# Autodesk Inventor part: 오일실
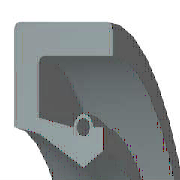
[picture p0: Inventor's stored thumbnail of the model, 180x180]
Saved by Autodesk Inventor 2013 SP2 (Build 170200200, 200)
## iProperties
IsCustomPart: 1
Created: 2015-10
Part Number: 오일실
Material: 고무
Description: 오일-실
Document SubType Name: Modeling
Standard: KS B 2804
Designer: mdu
Standards Organization: KS
Language: ko-KR
Size Designation: S - 25 38 8
Categories: <MemberInstance><Categories><Category DisplayName="샤프트 부품" InternalName="7f7aeb1f-a693-4053-b835-cee3144e0d98" Mnemonic="SHFT"><Category DisplayName="실링" Intern
Density: 0.93 g/cm^3
Mass: 2.23721 g
Surface Area: 37.0166 cm^2
Volume: 2.4056 cm^3
Author: mdu
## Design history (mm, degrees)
revolve "본체" stored, may be unused: angle "d17" = 90 deg
revolve "스프링1" stored, may be unused: angle "d18" = 90 deg
body "Solid1"
sketch "스케치1"
  geometry: L1 (0, 19)-(8, 19); L2 (8, 19)-(8, 17.75); L3 (8, 17.75)-(1.75, 17.75); L4 (0, 19)-(0, 14.6); L5 (0, 14.6)-(1.75, 14.25); L6 (1.75, 14.25)-(4.9, 12.5); L7 (4.9, 12.5)-(0, 12.5); L8 (6.3, 13.375)-(6.3, 14.6); L9 (0, 0)-(9.586, 0) reference; L10 (4.9, 12.5)-(6.3, 13.375); L11 (0, 18)-(0, -3) reference; L12 (-1.917, 0)-(11.503, 0) reference; L13 (4.2, 14.6)-(1.75, 15.09); L14 (1.75, 15.09)-(1.75, 17.75); L15 (6.3, 14.6)-(5.6, 14.6); C1 r 0.455 at (4.9, 14.6); A1 r 0.7 centre (4.9, 14.6) between (5.6, 14.6) and (4.2, 14.6)
  constraints: 26 end point, 5 horizontal alignment, 4 perpendicular, 2 centre point, 2 collinear, 2 horizontal, 2 parallel, 2 point on circle, 2 point on line, 2 vertical alignment, 1 coincident
  dimensions: "d0" = 38 diameter of L1 L9 (= SD2); "d1" = 26.75 diameter of L8.start L9 (= ABDM); "d2" = 1.25 distance of L1.end L2.end (computed from SD); "d3" = 0.91 diameter of C1 (= SPDI); "d4" = 1.4 diameter of A1 (= SPDA); "d5" = 25 diameter of L6.end L9 (= NND); "d6" = 28.5 diameter of L5.end L9 (= TKDM); "d7" = 29.2 diameter of L4.end L9 (= HLDM); "d8" = 4.9 distance from line of C1.centre L4 (= SPDST); "d9" = 6.3 distance between parallel lines of L8 L4 (= SDI); "d10" = 8 distance between parallel lines of L2 L4 (= SWDT); "d12" = 1.75 distance between parallel lines of L14 L4 (= SD)
fillet "모깎기1" dims "d11" = 0.3 (= RR)
other parameters: "SD2" = 38 [user parameter; used in 1 equation term], "SWDT" = 8 [user parameter; used in 1 equation term], "RR" = 0.3 [user parameter; used in 1 equation term], "SD" = 1.75 [user parameter; used in 2 equation terms], "NND" = 25 [user parameter; used in 1 equation term], "SPDA" = 1.4 [user parameter; used in 1 equation term], "SPDI" = 0.91 [user parameter; used in 1 equation term], "TKDM" = 28.5 [user parameter; used in 1 equation term], "HLDM" = 29.2 [user parameter; used in 1 equation term], "ABDM" = 26.75 [user parameter; used in 1 equation term], "SDI" = 6.3 [user parameter; used in 1 equation term], "SPDST" = 4.9 [user parameter; used in 1 equation term], "d13" = 0, "d14" = 0, "d15" = 0, "LAB" = 0.35 [user parameter]
